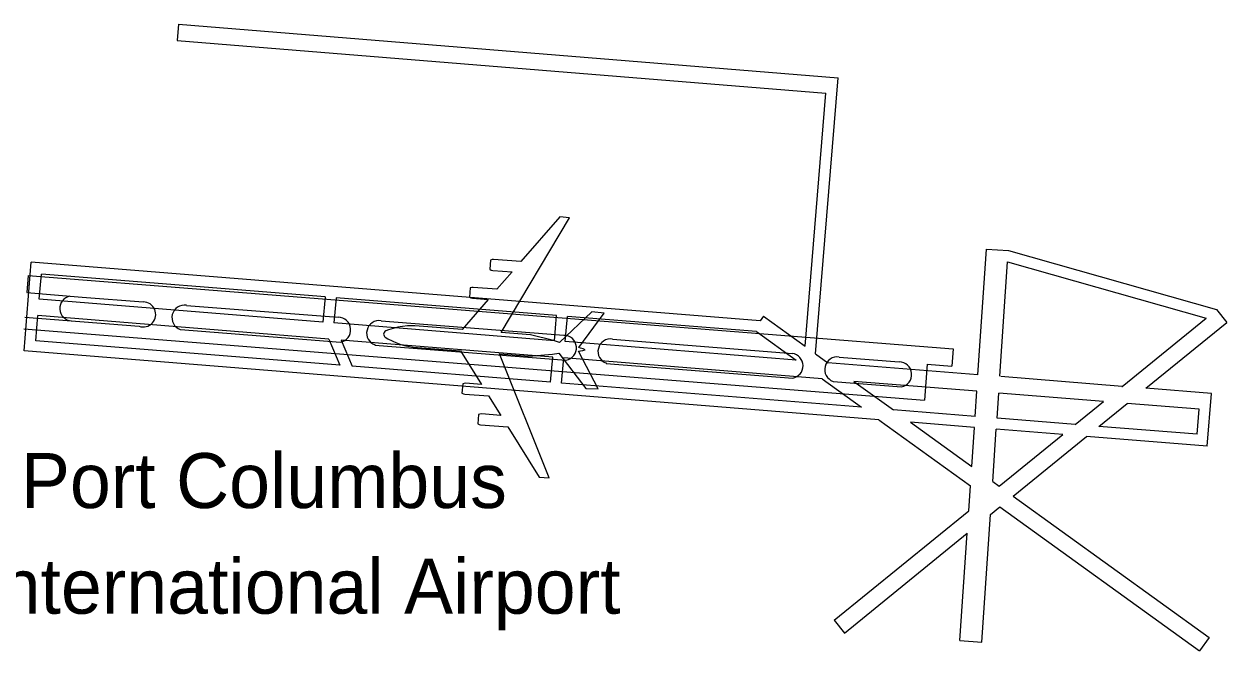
# Model space of a CAD drawing. Extents: x -9648 to 41057, y -12373 to 40276.
# Drawn here: x 30111 to 41057, y 9617 to 15324 of the extents above; entities that cross this region are included whole.
import ezdxf

# ---------------------------------------------------------------- set-up
doc = ezdxf.new("R2010")
doc.units = 0
doc.layers.add('SC_Scratch1', color=7, linetype='Continuous')

msp = doc.modelspace()

# ---------------------------------------------------------------- linework, layer by layer
at = {"layer": 'SC_Scratch1'}
for p, q in [((31517, 15324), (31504, 15174)), ((31517, 15324), (37519, 14835)), ((31504, 15174), (37407, 14693)), ((37314, 12321), (37519, 14835)), ((37219, 12390), (37407, 14693)), ((38791, 12131), (38868, 13275)), ((38868, 13275), (39068, 13262)), ((39068, 13262), (40962, 12724)), ((30111, 12349), (30176, 13156)), ((36808, 12622), (30176, 13156)), ((38990, 12119), (39061, 13160)), ((39061, 13160), (40867, 12647)), ((30149, 13035), (30136, 12879)), ((30149, 13035), (38566, 12367)), ((30249, 12819), (30268, 13048)), ((32851, 12840), (30268, 13048)), ((30136, 12879), (30640, 12839)), ((32829, 12611), (30249, 12819)), ((30640, 12839), (31195, 12795)), ((32851, 12840), (32829, 12611)), ((32950, 12832), (32929, 12603)), ((34956, 12671), (32950, 12832)), ((31588, 12763), (32969, 12654)), ((40962, 12724), (41057, 12608)), ((30118, 12655), (31158, 12573)), ((30219, 12440), (30237, 12670)), ((32884, 12456), (30237, 12670)), ((34936, 12441), (32929, 12603)), ((33360, 12623), (35023, 12491)), ((34936, 12441), (34956, 12671)), ((35035, 12433), (35056, 12663)), ((36776, 12524), (35056, 12663)), ((36839, 12664), (36808, 12622)), ((36839, 12664), (37219, 12390)), ((40102, 12025), (40867, 12647)), ((40318, 12008), (41057, 12608)), ((30110, 12550), (38303, 11899)), ((31533, 12543), (32990, 12427)), ((36776, 12524), (37137, 12264)), ((32984, 12218), (30219, 12440)), ((32884, 12456), (32984, 12218)), ((34923, 12292), (32997, 12447)), ((32997, 12447), (33097, 12208)), ((33304, 12402), (35043, 12264)), ((37137, 12264), (35035, 12433)), ((35465, 12456), (37103, 12325)), ((37889, 11722), (30111, 12349)), ((34902, 12063), (34923, 12292)), ((35002, 12055), (35022, 12284)), ((37372, 12095), (35022, 12284)), ((37314, 12321), (37425, 12241)), ((37528, 12292), (38074, 12248)), ((38566, 12367), (38554, 12210)), ((34902, 12063), (33097, 12208)), ((35409, 12235), (37105, 12100)), ((38791, 12131), (37425, 12241)), ((38329, 12228), (38303, 11899)), ((38329, 12228), (38554, 12210)), ((37732, 11835), (35002, 12055)), ((37372, 12095), (37732, 11835)), ((37472, 12071), (38094, 12022)), ((37660, 12071), (38021, 11812)), ((38781, 11981), (37660, 12071)), ((40102, 12025), (38999, 12114)), ((38765, 11752), (38781, 11981)), ((38965, 11736), (38980, 11965)), ((39933, 11888), (38980, 11965)), ((40101, 12025), (40102, 12025)), ((40917, 11960), (40318, 12008)), ((40878, 11481), (40917, 11960)), ((39675, 11678), (39933, 11888)), ((39891, 11661), (40150, 11871)), ((40805, 11818), (40150, 11871)), ((37889, 11722), (38723, 11121)), ((38765, 11752), (38021, 11812)), ((39675, 11678), (38965, 11736)), ((40786, 11589), (40805, 11818)), ((38177, 11699), (38734, 11297)), ((38758, 11652), (38177, 11699)), ((38734, 11297), (38758, 11652)), ((38926, 11159), (38958, 11636)), ((39562, 11587), (38958, 11636)), ((40786, 11589), (39891, 11661)), ((38984, 11117), (39562, 11587)), ((39110, 11026), (39779, 11570)), ((40878, 11481), (39779, 11570)), ((38707, 10892), (38723, 11121)), ((38926, 11159), (38984, 11117)), ((39110, 11026), (40896, 9739)), ((37481, 9896), (38707, 10892)), ((38827, 9698), (38905, 10860)), ((38905, 10860), (38989, 10928)), ((38989, 10928), (40808, 9617)), ((37575, 9780), (38693, 10688)), ((38627, 9711), (38693, 10688)), ((37481, 9896), (37575, 9780)), ((38627, 9711), (38827, 9698)), ((40896, 9739), (40808, 9617))]:
    msp.add_line(p, q, dxfattribs=at)
for points in [[(35217, 12358), (35197, 12367), (35175, 12374), (35158, 12378), (35388, 12691), (35277, 12705), (34984, 12425), (34929, 12444), (34719, 12495), (34453, 12516), (35074, 13561), (34985, 13568), (34632, 13161), (34383, 13180), (34370, 13179), (34356, 13175), (34350, 13091), (34362, 13084), (34375, 13081), (34551, 13067), (34414, 12910), (34197, 12927), (34184, 12926), (34170, 12922), (34164, 12838), (34176, 12831), (34190, 12828), (34333, 12817), (34096, 12544), (33668, 12578), (33599, 12577), (33553, 12572), (33512, 12564), (33427, 12541), (33403, 12530), (33395, 12524), (33388, 12517), (33381, 12502)], [(33381, 12502), (33386, 12487), (33391, 12479), (33398, 12472), (33421, 12457), (33501, 12421), (33540, 12406), (33584, 12395), (33652, 12383), (34081, 12350), (34272, 12043), (34129, 12054), (34115, 12053), (34102, 12049), (34095, 11965), (34108, 11958), (34121, 11955), (34338, 11938), (34448, 11761), (34273, 11775), (34259, 11774), (34246, 11770), (34239, 11686), (34252, 11679), (34265, 11676), (34513, 11657), (34799, 11199), (34888, 11192), (34437, 12322), (34704, 12301), (34919, 12318), (34976, 12328), (35222, 12006), (35334, 12002), (35156, 12347), (35174, 12349), (35196, 12353), (35217, 12358)]]:
    msp.add_lwpolyline(points, dxfattribs=at)
for centre, start, end in [((30550, 12735), 100.859, 265.3289), ((31195, 12680), 250.8121, 90.0002), ((31570, 12651), 80.9197, 250.812), ((32969, 12540), 280.1077, 90.0003), ((33342, 12510), 80.9197, 250.812), ((35023, 12376), 280.1078, 89.9997), ((35447, 12343), 80.9198, 250.812), ((37085, 12213), 280.1077, 80.9196), ((37510, 12179), 80.9194, 250.8121), ((38074, 12134), 280.1078, 90)]:
    msp.add_arc(centre, 114, start, end, dxfattribs=at)

# ---------------------------------------------------------------- texts
for s, p in [('Port Columbus', (30082, 10918)), ('International Airport', (29703, 9956))]:
    msp.add_text(s, height=499.99, rotation=0.0025, dxfattribs=at).set_placement(p)

doc.saveas('drawing.dxf')
